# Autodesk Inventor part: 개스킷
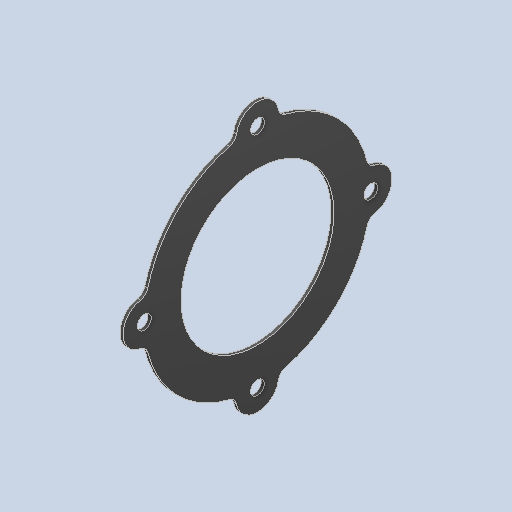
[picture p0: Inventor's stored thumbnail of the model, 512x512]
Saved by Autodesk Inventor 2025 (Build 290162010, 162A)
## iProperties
Created: 2024-08
Part Number: 개스킷
Material: 황동, 연질 노란색
Document SubType Name: Modeling
Designer: 학생
Density: 8.47 g/cm^3
Appearance: 기본값
Author: jhkim
Sending System: Autodesk Inventor 2025
Preprocessor: ST-DEVELOPER v20
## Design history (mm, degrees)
feature "솔리드2"
node "솔리드1"
